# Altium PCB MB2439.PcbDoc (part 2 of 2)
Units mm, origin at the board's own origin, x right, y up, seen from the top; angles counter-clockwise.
Board outline 43.1 x 47.12 mm, 4 copper layers (Top Layer, Internal 2, Internal 3, Bottom Layer), stack 1.565 mm thick; 79 components, 62 nets, 323 pads, 761 vias.
Unrouted connection lines stored in the file: 15.
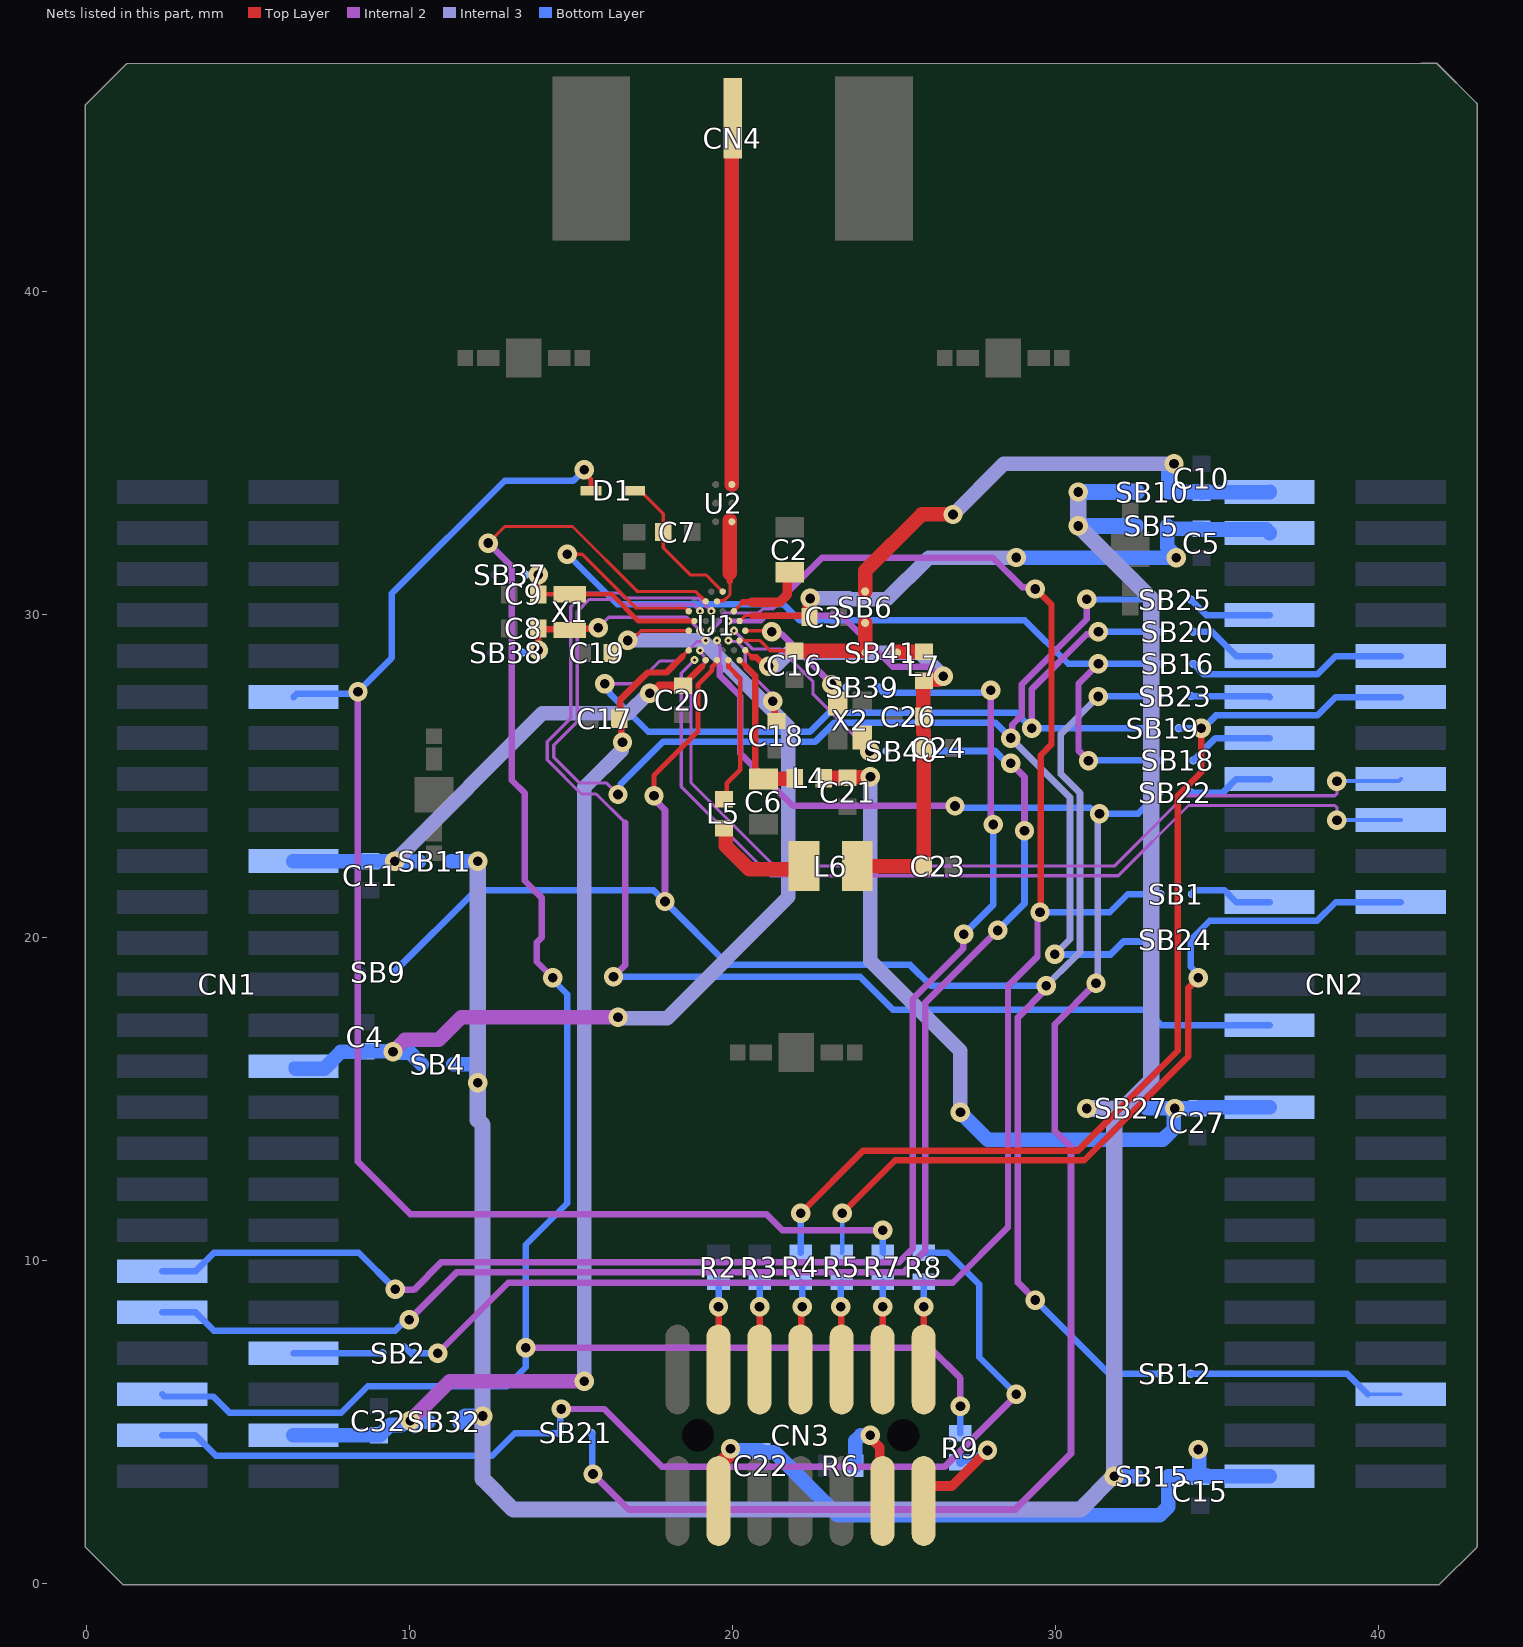
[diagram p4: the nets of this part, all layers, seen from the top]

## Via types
v1: diameter 0.6, hole 0.3, Top Layer to Bottom Layer, tented both sides, 747 vias
v2: diameter 0.25, hole 0.1, Top Layer to Internal 2, 14 vias

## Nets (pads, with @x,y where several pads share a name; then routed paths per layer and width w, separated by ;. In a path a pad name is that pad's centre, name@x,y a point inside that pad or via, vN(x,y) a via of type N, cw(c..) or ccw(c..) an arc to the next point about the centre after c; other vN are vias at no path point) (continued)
GPIO22: CN1.44 SB2.1 | length 2.8
  Bottom Layer w0.2: CN1.44@6.398,7.118 SB2.1@9.156,7.118
GPIO23: CN1.45 R9.1 U1.H2 | length 62.8
  Top Layer w0.1: v1(12.432,32.207) 12.944,32.72 15.039,32.72 17.055,30.703 18.86,30.703 U1.H2@19.163,30.4
  Internal 2 w0.2: v1(12.432,32.207) 13.161,31.478 13.161,24.864 13.557,24.467 13.557,21.755 14.093,21.218 14.093,20.005 13.929,19.841 13.929,19.246 v1(14.429,18.746) ; v1(13.593,7.293) 26.108,7.293 27.051,6.35 v1(27.051,5.477) v1@27.051,5.393
  Bottom Layer w0.2: CN1.45@2.334,5.848 2.403,5.78 3.914,5.78 4.414,5.28 7.878,5.28 8.694,6.096 13.001,6.096 13.593,6.687 13.593,10.48 14.876,11.762 14.876,18.234 14.429,18.681 v1(14.429,18.746) ; R9.1@27.051,4.641 v1(27.051,5.477)
GPIO24: CN1.47 R8.2 SB21.1 | length 35.5
  Internal 2 w0.2: v1(14.691,5.393) 16.019,5.393 17.803,3.609 26.571,3.609 v1@28.88,5.918
  Bottom Layer w0.2: CN1.47@2.334,4.578 3.363,4.578 3.997,3.944 12.55,3.944 13.249,4.644 14.657,4.644 14.657,5.359 v1(14.691,5.393) ; R8.2@25.917,10.229 26.655,10.229 27.635,9.249 27.635,6.991 v1(28.778,5.848)
GPIO28: CN2.7 SB25.1 | length 2.6
  Bottom Layer w0.2: SB25.1@34.186,30.457 34.664,29.978 CN2.7@36.624,29.978
GPIO29: CN2.9 SB20.2 | length 2.7
  Bottom Layer w0.2: SB20.2@34.261,29.461 34.843,29.461 35.596,28.708 CN2.9@36.624,28.708
GPIO30: CN2.10 SB16.2 | length 6.8
  Bottom Layer w0.2: SB16.2@34.261,28.466 34.587,28.14 38.104,28.14 38.673,28.708 CN2.10@40.688,28.708
GPIO31: CN2.11 SB23.1 | length 2.5
  Bottom Layer w0.2: SB23.1@34.186,27.47 36.593,27.47 CN2.11@36.624,27.438
GPIO32: CN2.12 R4.2 SB19.2 | length 32.6
  Top Layer w0.2: v1(22.103,11.455) 24.042,13.394 30.692,13.394 33.782,16.485 33.782,24.383 34.511,25.112 v1(34.511,26.474)
  Bottom Layer w0.2: R4.2@22.103,10.229 v1(22.103,11.455) ; SB19.2@33.811,26.474 v1(34.511,26.474) 34.568,26.474 34.964,26.87 38.104,26.87 38.673,27.438 CN2.12@40.688,27.438
GPIO33: CN2.13 SB18.2 | length 2.6
  Bottom Layer w0.2: SB18.2@34.261,25.479 34.95,26.168 CN2.13@36.624,26.168
GPIO34: CN2.15 SB22.1 | length 2.6
  Bottom Layer w0.2: SB22.1@34.186,24.483 35.181,24.483 35.596,24.898 CN2.15@36.624,24.898
GPIO37: CN2.21 SB1.1 | length 2.6
  Bottom Layer w0.2: SB1.1@34.223,21.336 34.223,21.35 34.288,21.415 34.288,21.457 35.228,21.457 35.596,21.088 CN2.21@36.624,21.088
GPIO38: CN2.22 R5.2 SB24.1 | length 24.8
  Top Layer w0.2: v1(23.393,11.455) 25.032,13.094 30.889,13.094 34.111,16.317 34.111,18.429 34.417,18.735 v1(34.417,18.746)
  Bottom Layer w0.15: R5.2@23.374,10.229 23.393,10.248 v1(23.393,11.455)
  Bottom Layer w0.2: v1(34.417,18.746) 34.417,18.854 34.186,19.085 SB24.1@34.186,19.921 34.774,20.51 38.094,20.51 38.673,21.088 CN2.22@40.688,21.088
GPIO42: CN2.27 U1.G3 | length 38.9
  Internal 2 w0.1: 16.667,23.54 15.77,24.437 15.315,24.437 14.258,25.494 14.258,26.061 14.982,26.785 14.982,30.235 15.41,30.663 16.494,30.663 16.649,30.509 18.44,30.509 18.93,30.509 v2@19.338,30.101
  Internal 2 w0.2: v1(16.31,18.778) 16.667,19.135 16.667,23.54
  Bottom Layer w0.2: v1(16.31,18.778) 23.942,18.778 24.957,17.763 32.802,17.763 33.286,17.278 CN2.27@36.624,17.278
  other v2: 19.338,30.097
GPIO56: CN2.46 SB12.1 | length 6.8
  Bottom Layer w0.1: CN2.46@39.66,5.848 CN2.46@40.688,5.848
  Bottom Layer w0.2: SB12.1@34.186,6.483 39.025,6.483 CN2.46@39.66,5.848
NetC2_2: C2.2 U1.C3 | length 2.8
  Top Layer w0.1: U1.C3@20.038,30.097 20.312,30.372 ; C2.2@21.689,31.031 21.959,31.3 C2.2@22.1,31.3
  Top Layer w0.2: 20.312,30.372 20.599,30.372
  Top Layer w0.3: 20.599,30.372 21.45,30.372 21.689,30.61 C2.2@21.689,31.031
NetC6_1: C6.1 L4.2 U1.B8 | length 5
  Top Layer w0.15: U1.B8@20.213,28.582 20.416,28.379
  Top Layer w0.2: 20.416,28.379 20.697,28.098 20.697,25.12 20.917,24.9 C6.1@20.955,24.9
  Top Layer w0.45: C6.1@20.955,24.9 20.968,24.912 21.906,24.912 L4.2@21.919,24.925
NetC7_2: C7.2 D1.1 U1.E1 | length 4.6
  Top Layer w0.1: D1.1@16.956,33.831 17.131,33.831 17.847,33.115 C7.2@17.847,32.546 17.847,32.059 18.686,31.22 19.171,31.22 19.479,30.912 U1.E1@19.688,30.703
NetC8_2: C8.2 SB38.1 U1.J5 X1.2 | length 6.6
  Top Layer w0.2: v1(13.979,28.885) C8.2@13.979,29.567 14.002,29.544 14.934,29.544 X1.2@14.958,29.52 14.988,29.55 15.802,29.55 v1(15.832,29.58)
  Internal 2 w0.1: v1(15.832,29.58) 16.161,29.909 18.44,29.909 18.57,29.909 v2(18.988,29.491)
  Bottom Layer w0.15: SB38.1@13.48,28.816 13.909,28.816 v1(13.979,28.885)
NetC9_2: C9.2 SB37.1 U1.K4 X1.1 | length 5.8
  Top Layer w0.15: v1(13.979,31.228) C9.2@13.979,30.62 X1.1@14.958,30.62 16.254,30.62 17.08,29.794 U1.K4@18.799,29.794
NetC16_2: C16.2 SB6.2 SB41.1 U1.B6 | length 4.8
  Top Layer w0.1: U1.B6@20.213,29.188 20.848,29.188 21.161,28.875 C16.2@21.919,28.875
  Top Layer w0.45: C16.2@21.919,28.875 24.054,28.875 24.101,28.921 SB6.2@24.101,29.734
NetC23_2: C23.2 C24.1 C26.1 L6.2 L7.2 U1.A7 U1.D4 | length 22.7
  Top Layer w0.1: U1.A7@20.388,28.885 20.599,28.674
  Top Layer w0.2: 20.599,28.674 20.727,28.674 21.005,28.395 v1(21.113,28.395)
  Top Layer w0.45: L6.2@23.859,22.205 C23.2@25.909,22.205 C24.1@25.909,25.826 ; C24.1@25.915,25.864 25.915,26.355 25.907,26.363 25.907,26.834 25.907,27.936 25.947,27.975 26.375,27.975 26.482,28.082 v1(26.522,28.082)
  Internal 2 w0.15: v2(19.863,29.794) 20.873,29.794 21.015,29.936 21.359,29.936 21.374,29.952 ; v1@26.401,28.082 v1(26.522,28.082)
  Internal 2 w0.2: 21.374,29.952 23.38,29.952 24.955,28.377 26.106,28.377 v1@26.401,28.082
  Internal 3 w0.45: v1(21.113,28.395) 21.142,28.424 21.345,28.424 21.736,28.816 25.789,28.816 v1(26.522,28.082)
NetCN3_4: CN3.4 R2.1 | length 2.7
  Top Layer w0.2: CN3.4@19.561,6.614 v1(19.561,8.563)
  Bottom Layer w0.2: v1(19.561,8.563) R2.1@19.561,9.329
NetCN3_6: CN3.6 R3.1 | length 2.7
  Top Layer w0.2: CN3.6@20.831,6.614 v1(20.831,8.563)
  Bottom Layer w0.2: v1(20.831,8.563) R3.1@20.831,9.328
NetCN3_8: CN3.8 R4.1 | length 2.8
  Top Layer w0.2: CN3.8@22.101,6.614 22.125,6.638 22.125,8.539 v1(22.149,8.563)
  Bottom Layer w0.2: R4.1@22.103,9.329 22.149,9.283 v1(22.149,8.563)
NetCN3_10: CN3.10 R5.1 | length 2.7
  Top Layer w0.2: v1(23.346,8.563) 23.359,8.551 23.359,6.627 CN3.10@23.371,6.614
  Bottom Layer w0.2: v1(23.346,8.563) 23.346,9.301 R5.1@23.374,9.329
NetCN3_11: CN3.11 R6.2 | length 3.5
  Top Layer w0.3: v1(24.259,4.579) 24.259,4.498 24.557,4.2 24.557,2.629 CN3.11@24.641,2.544
  Bottom Layer w0.3: v1@23.971,4.578 24.258,4.578 v1(24.259,4.579)
  Bottom Layer w0.45: R6.2@23.795,3.631 23.795,4.403 v1@23.971,4.578
NetCN3_12: CN3.12 R7.1 | length 2.7
  Top Layer w0.2: CN3.12@24.641,6.614 24.644,6.616 24.644,8.561 v1(24.646,8.563)
  Bottom Layer w0.2: v1(24.646,8.563) R7.1@24.646,9.329
NetCN3_13: CN3.13 R9.2 | length 3.8
  Top Layer w0.3: CN3.13@25.911,2.544 25.911,2.805 26.115,3.008 26.786,3.008 v1(27.888,4.109)
  Bottom Layer w0.3: R9.2@27.057,3.747 27.156,3.846 27.562,3.846 27.826,4.109 v1(27.888,4.109)
NetCN3_14: CN3.14 R8.1 | length 2.7
  Top Layer w0.2: CN3.14@25.911,6.614 25.914,6.617 25.914,8.561 v1(25.917,8.563)
  Bottom Layer w0.2: v1(25.917,8.563) R8.1@25.917,9.329
NetCN4_1: CN4.1 U2.A3 | length 11.4
  Top Layer w0.45: U2.A3@19.972,34.02 19.972,45.332 CN4.1@20,45.36
NetL5_1: L5.1 U1.D8 | length 4.7
  Top Layer w0.15: L5.1@19.728,24.275 19.815,24.362 19.815,24.772 20.235,25.192 20.235,28.01 19.871,28.374 19.871,28.379 U1.D8@19.871,28.57
NetL5_2: L5.2 L6.1 | length 3.3
  Top Layer w0.45: L5.2@19.728,23.375 19.747,23.375 19.777,23.345 19.777,22.835 20.508,22.105 21.959,22.105 22.06,22.205 L6.1@22.209,22.205
NetL7_1: L7.1 SB41.2 | length 0.8
  Top Layer w0.3: SB41.2@25.088,28.816 SB41.2@25.118,28.845
  Top Layer w0.45: SB41.2@25.118,28.845 L7.1@25.917,28.845
NetSB1_2: SB1.2 SB2.2 U1.G5 | length 56.3
  Top Layer w0.2: v1(29.367,30.785) 29.384,30.785 29.871,30.298 29.871,25.977 29.534,25.64 29.534,20.797 v1(29.515,20.777)
  Internal 2 w0.1: v2(19.338,29.491) 19.338,29.495 19.613,29.77 19.613,29.898 19.759,30.044 20.599,30.044 20.804,30.044 20.921,30.161 21.123,30.161 21.173,30.211
  Internal 2 w0.2: v1(10.866,7.118) 13.051,9.304 26.809,9.304 28.524,11.019 28.524,18.49 29.438,19.404 29.438,20.701 v1(29.515,20.777) ; 21.223,30.211 22.765,31.753 28.052,31.753 28.97,30.836 29.316,30.836 v1(29.367,30.785)
  Bottom Layer w0.2: 9.809,7.341 SB2.2@10.081,7.068 ; SB2.2@10.131,7.118 v1(10.866,7.118) ; v1(29.515,20.777) 31.671,20.777 32.229,21.336 SB1.2@33.248,21.336
NetSB4_1: SB4.1 SB5.1 SB10.1 SB11.1 SB15.1 SB27.1 SB32.1 | length 81
  Internal 3 w0.5: v1@12.087,22.357 12.103,22.34 v1(12.103,15.494) 12.103,14.346 12.255,14.194 v1(12.255,5.173) 12.255,3.234 13.21,2.279 30.759,2.279 31.788,3.308 v1(31.815,3.308) 31.815,14.68 ; v1(30.7,33.788) v1(30.7,32.738) 32.959,30.479 32.959,15.569 31.967,14.577 31.864,14.68 31.815,14.68 ; 31.294,14.719 30.982,14.719 v1(30.963,14.699) 30.982,14.68 31.815,14.68
  Bottom Layer w0.45: SB11.1@11.266,22.358 12.101,22.358 v1(12.103,22.357) ; SB4.1@11.347,16.07 11.349,16.072 12.024,16.072 ; v1(31.815,3.308) SB15.1@32.511,3.308
  Bottom Layer w0.5: SB32.1@11.559,4.998 11.715,5.154 12.236,5.154 v1(12.255,5.173) ; 12.024,16.072 12.084,16.012 12.084,15.513 v1(12.103,15.494) ; v1(30.7,32.738) SB5.1@32.481,32.738 ; v1(30.7,33.788) SB10.1@32.509,33.788 ; v1(30.963,14.699) SB27.1@31.85,14.699
NetSB9_2: SB9.2 SB12.2 SB23.2 U1.F8 | length 58
  Top Layer w0.15: v1(17.563,24.381) 17.563,25.013 18.922,26.372 18.922,27.826 19.363,28.267 19.363,28.378 19.503,28.518 19.503,28.573 U1.F8@19.513,28.582
  Internal 2 w0.21: v1(17.563,24.381) 17.563,24.275 17.901,23.937 v1(17.901,21.107) ; v1(29.367,8.765) 28.829,9.304 28.829,17.515 29.707,18.393 v1(29.707,18.498)
  Internal 3 w0.21: v1(29.707,18.498) 30.173,18.965 30.181,18.965 30.752,19.535 30.752,24.462 30.159,25.054 30.159,26.299 v1(31.318,27.457)
  Bottom Layer w0.21: SB9.2@9.513,18.921 12.048,21.457 17.551,21.457 v1(17.901,21.107) 19.862,19.146 25.488,19.146 26.136,18.498 v1(29.707,18.498) ; v1(29.367,8.765) 31.649,6.483 SB12.2@33.211,6.483 ; v1(31.318,27.457) 31.325,27.464 33.205,27.464 SB23.2@33.211,27.47
NetSB16_1: SB16.1 SB18.1 U1.L3 | length 30
  Top Layer w0.1: v1(14.878,31.857) 15.335,31.857 16.992,30.2 18.529,30.2 18.632,30.097 U1.L3@18.638,30.097
  Internal 2 w0.2: v1(31.015,25.466) 31.015,25.476 30.708,25.783 30.708,27.849 v1(31.325,28.466)
  Bottom Layer w0.2: v1(14.878,31.857) 16.422,30.313 18.44,30.313 20.599,30.313 21.574,30.313 22.076,29.811 29.046,29.811 30.392,28.466 v1(31.325,28.466) SB16.1@33.286,28.466 ; v1(31.015,25.466) 31.028,25.479 SB18.1@33.286,25.479
NetSB19_1: SB19.1 SB20.1 U1.H6 | length 27.6
  Internal 2 w0.1: v1(16.039,27.848) 17.039,27.848 17.747,28.556 18.3,28.556 18.44,28.696 18.904,29.16 19.134,29.16 v2(19.163,29.188)
  Internal 2 w0.2: v1(29.255,26.474) 29.255,27.675 30.965,29.385 31.248,29.385 v1(31.325,29.461)
  Bottom Layer w0.2: v1(16.039,27.848) 16.039,27.74 16.192,27.587 16.192,27.552 17.383,26.361 22.39,26.361 22.979,26.949 27.217,26.949 28.78,26.949 v1(29.255,26.474) SB19.1@32.836,26.474 ; v1(31.325,29.461) SB20.1@33.286,29.461
NetSB21_2: SB21.2 SB22.2 U1.F6 | length 55.7
  Internal 2 w0.1: v2(19.513,29.188) 19.513,29.148 19.604,29.057 19.604,28.379
  Internal 2 w0.2: 19.604,28.379 19.604,28.095 20.233,27.466 20.233,25.69 21.857,24.066 v1(26.881,24.066)
  Internal 2 w0.21: v1(15.672,3.378) 16.771,2.279 28.746,2.279 30.477,4.01 30.477,13.502 29.972,14.007 29.972,17.301 v1(31.249,18.578)
  Internal 3 w0.21: v1(31.249,18.578) 31.304,18.633 31.304,23.77 v1(31.359,23.825)
  Bottom Layer w0.1: SB21.2@15.622,4.654 SB21.2@15.647,4.629 ; v1@15.647,3.403 v1(15.672,3.378)
  Bottom Layer w0.2: v1@15.647,3.403 SB21.2@15.647,4.629 ; v1(26.881,24.066) 26.939,24.008 31.069,24.008 31.251,23.825 32.553,23.825 SB22.2@33.211,24.483
NetSB24_2: SB24.2 SB25.2 U1.J3 | length 43.4
  Internal 2 w0.1: v1(16.449,24.42) 16.093,24.776 15.259,24.776 14.458,25.577 14.458,25.951 15.182,26.676 15.182,30.082 15.564,30.463 16.411,30.463 16.566,30.309 18.776,30.309 v2(18.988,30.097)
  Internal 2 w0.2: v1(28.607,26.168) 28.657,26.218 28.657,26.583 28.955,26.881 28.955,27.839 30.963,29.846 v1(30.963,30.463)
  Internal 3 w0.21: v1(28.607,26.168) 30.442,24.334 30.442,19.94 v1(29.972,19.47)
  Bottom Layer w0.2: v1(16.449,24.42) 16.525,24.496 16.525,24.738 17.848,26.061 22.561,26.061 23.149,26.649 28.126,26.649 v1(28.607,26.168) ; v1(30.963,30.463) 30.966,30.46 33.208,30.46 SB25.2@33.211,30.457 ; 32.753,19.869 32.845,19.869 32.897,19.921 SB24.2@33.211,19.921
  Bottom Layer w0.21: v1(29.972,19.47) 31.703,19.469 32.103,19.869 32.753,19.869
NetSB39_1: SB39.1 U1.A5 X2.3 | length 4
  Top Layer w0.1: U1.A5@20.388,29.491 21.181,29.491 v1(21.211,29.461)
  Top Layer w0.2: v1@23.076,27.818 23.068,27.81 23.068,27.427 X2.3@23.257,27.238
  Internal 2 w0.2: v1(21.211,29.461) 21.288,29.385 21.525,29.385 23.068,27.841 v1(23.068,27.826)
NetSB40_1: SB40.1 U1.C5 X2.1 | length 6
  Internal 2 w0.1: v2@20.041,29.491 20.041,29.488 20.599,28.93 21.477,28.93 22.488,27.918 22.488,27.523 v1(24.247,25.765)
  other v2: 20.038,29.491
NetU1_F2: U1.F2 U2.A1 | length 2.8
  Top Layer w0.1: U1.F2@19.513,30.4 19.532,30.419 19.722,30.419 19.915,30.612 19.915,31.02
  Top Layer w0.2: 19.915,31.02 19.915,31.265
  Top Layer w0.45: U2.A1@19.913,32.918 19.913,31.325 19.915,31.323 19.915,31.265
NRST: CN1.12 D1.2 R7.2 | length 46.2
  Top Layer w0.15: v1(15.406,34.475) 15.406,34.38 15.606,34.179 D1.2@15.606,33.831
  Internal 2 w0.2: v1(8.395,27.601) 8.395,13.049 10.016,11.428 21.039,11.428 21.539,10.928 v1(24.646,10.928)
  Bottom Layer w0.2: CN1.12@6.398,27.438 6.502,27.542 8.337,27.542 v1(8.395,27.601) 9.444,28.65 9.444,30.643 12.938,34.138 15.068,34.138 v1(15.406,34.475) ; R7.2@24.646,10.229 v1(24.646,10.928)
OSC_IN: CN1.39 SB39.2 | length 46.4
  Internal 2 w0.21: v1@9.569,9.083 10.125,9.083 10.981,9.94 25.156,9.94 25.578,10.362 25.578,18.097 27.142,19.661 27.142,20.082 v1(27.156,20.096) ; v1(27.991,27.645) 27.991,23.812 27.996,23.807 27.996,23.569 v1(28.07,23.494)
  Bottom Layer w0.21: CN1.39@2.334,9.658 3.363,9.658 3.936,10.232 8.42,10.232 v1(9.554,9.097) v1@9.542,9.085 ; SB39.2@24.496,27.74 24.661,27.575 27.921,27.575 v1(27.991,27.645) ; v1(27.156,20.096) 28.07,21.011 v1(28.07,23.494)
OSC_OUT: CN1.41 SB40.2 | length 44.5
  Internal 2 w0.21: v1(9.982,8.153) 11.459,9.63 25.302,9.63 25.959,10.287 25.959,17.968 v1(28.203,20.212) ; v1(28.607,25.387) 29.034,24.959 v1(29.034,23.3)
  Bottom Layer w0.21: CN1.41@2.334,8.388 3.363,8.388 3.936,7.815 9.538,7.815 9.877,8.153 v1(9.982,8.153) ; SB40.2@25.736,25.765 28.123,25.765 28.502,25.387 v1(28.607,25.387) ; v1(28.203,20.212) 29.034,21.044 v1(29.034,23.3)
USB_FS_N: CN2.18 U1.K8 | length 28.8
  Internal 2 w0.1: v2(18.813,28.582) 18.61,28.379 18.408,28.178 18.408,24.665 21.17,21.903 31.937,21.903 34.114,24.081 38.651,24.081 38.71,24.022 v1(38.71,23.628)
  Bottom Layer w0.127: v1(38.71,23.628) CN2.18@40.688,23.628
USB_FS_P: CN2.16 U1.J7 | length 28.7
  Internal 2 w0.1: v2@18.989,28.877 18.989,28.843 19.06,28.771 19.06,28.759 19.113,28.707 19.113,28.458 19.034,28.379 18.708,28.053 18.708,24.789 21.294,22.203 31.812,22.203 33.99,24.381 38.651,24.381 38.71,24.439 v1(38.71,24.833)
  Bottom Layer w0.127: v1(38.71,24.833) 40.623,24.833 CN2.16@40.688,24.898
  other v2: 18.992,28.88
VDD4: C4.2 C18.1 C19.1 CN1.30 SB4.2 U1.D6 U1.L5 | length 35.9
  Top Layer w0.1: C19.1@16.261,28.804 16.261,28.792 16.306,28.747 v1(16.751,29.192) 16.86,29.192 17.159,29.491 U1.L5@18.638,29.491
  Top Layer w0.2: v1(21.239,27.308) 21.295,27.252 21.295,26.753 C18.1@21.351,26.697
  Internal 2 w0.1: v2(19.863,29.188) 19.891,29.159 20.117,29.159 20.388,28.889 20.388,28.323 21.159,27.552 21.159,27.389 v1(21.239,27.308)
  Internal 2 w0.45: v1(9.481,16.459) 9.85,16.828 10.901,16.828 11.597,17.524 v1(16.449,17.524)
  Internal 3 w0.45: v1(16.449,17.524) 16.477,17.495 17.969,17.495 21.726,21.252 21.726,26.521 19.868,28.379 19.056,29.192 v1@16.791,29.192
  Bottom Layer w0.3: CN1.30@6.398,16.008 CN1.30@6.476,15.931
  Bottom Layer w0.45: CN1.30@6.476,15.931 7.349,15.931 7.867,16.448 8.607,16.448 C4.2@8.627,16.469 v1@9.512,16.469 ; v1(9.481,16.459) 9.51,16.431 10.013,16.431 SB4.2@10.372,16.07 SB4.2@10.372,16.07
VDD5: C3.1 C5.2 CN2.3 SB5.2 U1.B4 | length 19.1
  Top Layer w0.1: U1.B4@20.213,29.794 20.38,29.961 20.599,29.961
  Top Layer w0.2: 20.599,29.961 22.33,29.961 C3.1@22.377,29.914
  Top Layer w0.45: C3.1@22.377,29.914 22.389,29.926 22.389,30.481 v1(22.4,30.493)
  Internal 3 w0.45: v1(22.4,30.493) 23.593,30.493 23.622,30.463 24.774,30.463 26.069,31.759 v1(28.78,31.759)
  Bottom Layer w0.45: v1(28.78,31.759) v1(33.736,31.757) ; v1(33.736,31.757) 33.736,31.798 33.456,32.078 SB5.2@33.456,32.738 33.537,32.657 C5.2@34.519,32.657 34.549,32.627 36.516,32.627 CN2.3@36.624,32.518
VDD8: C17.1 C32.2 CN1.48 SB32.2 U1.L7 | length 34.9
  Top Layer w0.1: 18.44,28.688 U1.L7@18.638,28.885
  Top Layer w0.2: v1(16.586,26.039) 16.554,26.071 16.554,26.702 16.464,26.791 16.512,26.839 16.512,27.346 17.223,28.057 17.226,28.057 17.367,28.199 17.951,28.199 18.44,28.688
  Internal 2 w0.45: v1(10.013,5.027) 11.24,6.254 v1(15.406,6.254)
  Internal 3 w0.45: v1(15.406,6.254) 15.406,24.639 16.558,25.791 16.558,26.01 v1(16.586,26.039)
  Bottom Layer w0.45: CN1.48@6.398,4.578 9.043,4.578 9.069,4.577 9.389,4.897 9.729,4.897 9.831,4.998 9.984,4.998 v1(10.013,5.027) 10.041,4.998 SB32.2@10.584,4.998 ; v1@10.013,4.987 v1@10.147,4.853
VDD9: C21.1 C27.2 CN2.31 L4.1 SB27.2 | length 24.6
  Top Layer w0.45: L4.1@22.819,24.925 22.829,24.935 23.549,24.935 23.575,24.962 24.215,24.962 v1@24.243,24.989
  Internal 3 w0.45: v1(24.264,24.969) 24.264,19.277 27.051,16.49 v1(27.051,14.577)
  Bottom Layer w0.45: v1(27.051,14.577) 27.903,13.726 33.317,13.726 33.663,14.072 33.663,14.671 v1(33.692,14.699) ; SB27.2@32.825,14.699 v1(33.692,14.699) ; CN2.31@36.624,14.738 34.456,14.738 34.417,14.699 C27.2@34.392,14.699 v1(33.692,14.699)
VDD10: C10.2 CN2.1 SB6.1 SB10.2 | length 15.7
  Top Layer w0.45: SB6.1@24.101,30.709 24.101,31.347 25.847,33.093 v1(26.822,33.093)
  Internal 3 w0.45: v1(26.822,33.093) 28.391,34.661 v1(33.663,34.661)
  Bottom Layer w0.45: v1(33.663,34.661) 33.663,34.62 33.484,34.441 SB10.2@33.484,33.788 34.491,33.788 C10.2@34.519,33.761 34.532,33.775 36.611,33.775 CN2.1@36.624,33.788
VDD15: C15.2 C22.1 CN2.49 CN3.3 SB15.2 | length 21.2
  Top Layer w0.45: CN3.3@19.561,2.544 19.561,3.648 19.903,3.989 19.903,4.13 v1(19.931,4.159)
  Bottom Layer w0.45: v1(19.931,4.159) 19.972,4.159 20.02,4.111 20.857,4.111 20.917,4.051 21.299,4.051 23.249,2.101 33.222,2.101 33.486,2.365 SB15.2@33.486,3.308 C15.2@34.464,3.308 ; v1(34.417,4.14) 34.448,4.109 34.448,3.325 C15.2@34.464,3.308 ; C15.2@34.478,3.295 C15.2@34.464,3.308 ; C15.2@34.478,3.308 CN2.49@36.624,3.308
VDDA: C11.2 C20.2 CN1.20 SB11.2 U1.H8 | length 16.1
  Top Layer w0.1: 19.034,28.379 19.163,28.508 U1.H8@19.163,28.582
  Top Layer w0.2: C20.2@18.492,27.8 18.635,27.942 18.635,27.98 19.034,28.379
  Top Layer w0.3: v1(17.431,27.559) 17.512,27.559 17.725,27.771 18.325,27.771 18.341,27.787 C20.2@18.455,27.787
  Internal 3 w0.45: v1(9.531,22.358) 14.106,26.933 16.765,26.933 17.391,27.559 v1(17.431,27.559)
  Bottom Layer w0.45: CN1.20@6.398,22.358 v1(9.531,22.358) SB11.2@10.291,22.358
pads on no net: CN1.2 CN1.3 CN1.4 CN1.5 CN1.8 CN1.10 CN1.11 CN1.16 CN1.18 CN1.19 CN1.21 CN1.23 CN1.24 CN1.27 CN1.29 CN1.32 CN1.36 CN1.38 CN1.42 CN1.43 CN1.50 CN2.4 CN2.5 CN2.6 CN2.17 CN2.19 CN2.23 CN2.24 CN2.25 CN2.28 CN2.29 CN2.30 CN2.33 CN2.34 CN2.35 CN2.36 CN2.37 CN2.39 CN2.40 CN2.41 CN2.42 CN2.43 CN2.45 CN2.47 CN2.48 CN3.1 CN3.2 CN3.9 CN3.NPTH1 CN3.NPTH2

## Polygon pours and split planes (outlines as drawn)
GND on Top Layer "GND_L01_P000" (solid, pour order 0): -0.036,1.103 cw(c0,1.139) -0.05,1.139 -0.05,45.75 -0.05,45.755 cw(c0,45.755) -0.035,45.791 1.209,47.036 cw(c1.245,47) 1.245,47.05 41.326,47.066 41.78,47.066 cw(c41.78,47.015) 41.816,47.051 43.03,45.837 cw(c43.001,45.795) 43.051,45.795 cw(c43.002,45.795) 43.05,45.785 43.05,1.151 cw(c43.002,1.141) 43.051,1.141 cw(c43.001,1.141) 43.037,1.105 41.888,-0.036 cw(c41.852,0) 41.852,-0.05 1.139,-0.05 cw(c1.139,0) 1.103,-0.036
GND on Internal 3 "GND_L03_P002" (solid, pour order 2): -0.036,1.103 cw(c0,1.139) -0.05,1.139 -0.05,45.75 -0.05,45.755 cw(c0,45.755) -0.035,45.791 1.209,47.036 cw(c1.245,47) 1.245,47.05 41.326,47.066 41.78,47.066 cw(c41.78,47.015) 41.816,47.051 43.03,45.837 cw(c43.001,45.795) 43.051,45.795 cw(c43.002,45.795) 43.05,45.785 43.05,1.151 cw(c43.002,1.141) 43.051,1.141 cw(c43.001,1.141) 43.037,1.105 41.888,-0.036 cw(c41.852,0) 41.852,-0.05 1.139,-0.05 cw(c1.139,0) 1.103,-0.036
GND on Bottom Layer "GND_L04_P003" (solid, pour order 3): -0.036,1.103 cw(c0,1.139) -0.05,1.139 -0.05,45.75 -0.05,45.755 cw(c0,45.755) -0.035,45.791 1.209,47.036 cw(c1.245,47) 1.245,47.05 41.326,47.066 41.78,47.066 cw(c41.78,47.015) 41.816,47.051 43.03,45.837 cw(c43.001,45.795) 43.051,45.795 cw(c43.002,45.795) 43.05,45.785 43.05,1.151 cw(c43.002,1.141) 43.051,1.141 cw(c43.001,1.141) 43.037,1.105 41.888,-0.036 cw(c41.852,0) 41.852,-0.05 1.139,-0.05 cw(c1.139,0) 1.103,-0.036
GND on Internal 2 "GND_L02_P001" (solid, pour order 1): -0.036,1.103 cw(c0,1.139) -0.05,1.139 -0.05,45.75 -0.05,45.755 cw(c0,45.755) -0.035,45.791 1.209,47.036 cw(c1.245,47) 1.245,47.05 41.326,47.066 41.78,47.066 cw(c41.78,47.015) 41.816,47.051 43.03,45.837 cw(c43.001,45.795) 43.051,45.795 cw(c43.002,45.795) 43.05,45.785 43.05,1.151 cw(c43.002,1.141) 43.051,1.141 cw(c43.001,1.141) 43.037,1.105 41.888,-0.036 cw(c41.852,0) 41.852,-0.05 1.139,-0.05 cw(c1.139,0) 1.103,-0.036

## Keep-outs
Keep-Out Layer:
  lines w0.1: 1.245,46.99 41.859,46.99 ; 43.001,1.143 43.001,45.798 41.781,47.018 1.261,47.018 0.001,45.757 0.001,1.141 1.14,0.002 11.318,0.002 11.329,0.013 16.413,0.013 26.58,0.013 31.664,0.013 31.675,0.002 41.853,0.002 42.505,0.65 43.002,1.143

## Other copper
Top Layer:
  pour cut-out: 2.179,43.064 2.179,45.096 7.656,45.096 7.656,43.064
  pour cut-out: 20.568,30.189 20.468,30.22 20.397,30.22 20.18,30.259 19.857,30.426 19.481,30.846 18.415,30.886 18.413,30.884 18.413,28.392 20.597,28.392 20.604,28.399 20.604,30.259
  text "1" at 2.422,43.483 h2
  text ".Layer_Name" at -14.442,-71.206 h3
  text ".GTL" at 27.253,-71.206 h3
Internal 2:
  pour cut-out: 2.179,43.064 2.179,45.096 7.656,45.096 7.656,43.064
  pour cut-out: 18.8,47 21.2,47 21.2,29.794 18.8,29.794
  text "2" at 3.664,43.483 h2
  text ".Layer_Name" at -14.442,-71.206 h3
  text ".G1" at 27.253,-71.206 h3
Internal 3:
  pour cut-out: 2.179,43.064 2.179,45.096 7.656,45.096 7.656,43.064
  text "3" at 5.17,43.507 h2
Bottom Layer:
  pour cut-out: 2.179,43.064 2.179,45.096 7.656,45.096 7.656,43.064
  text "4" at 6.508,43.536 h2
  text ".GBL" at 16.05,-71.238 h3
  text ".Layer_Name" at 57.364,-71.238 h3

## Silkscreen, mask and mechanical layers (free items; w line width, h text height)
Top Overlay:
  text "J" at 34.163,40.615 h10
  text "K" at 1.803,36.652 h10
  text "MB2439B" at 32.512,1.337 h2.5
  text ".Layer_Name" at -14.442,-71.206 h3
  text ".GTO" at 27.253,-71.206 h3
Board Layer Stack Bottom Overlay:
  text "H" at 32.868,42.621 h7.62
  text "I" at 40.488,42.113 h7.62
  text "G" at 7.925,38.76 h7.62
  text ".GBO" at 16.05,-71.238 h3
  text ".Layer_Name" at 57.364,-71.238 h3
Top Paste:
  text ".Layer_Name" at -14.442,-71.206 h3
  text ".GTP" at 27.253,-71.206 h3
Bottom Paste:
  text ".GBP" at 16.05,-71.238 h3
  text ".Layer_Name" at 57.364,-71.238 h3
Top Solder:
  lines w0.75: 17.831,37.929 10.75,37.929 10.75,16.5 32.25,16.5 32.25,37.96 22.649,37.96
  text ".Layer_Name" at -14.442,-71.206 h3
  text ".GTS" at 27.253,-71.206 h3
Board Layer Stack Bottom Solder:
  text ".GBS" at 16.05,-71.238 h3
  text ".Layer_Name" at 57.364,-71.238 h3
M1-Board Shape:
  lines w0.1: 43.002,1.143 43.002,45.798 ; 43.003,1.143 41.854,0.002 1.141,0.002 0.002,1.141 0.002,45.752 1.252,47.002 41.328,47.018 41.782,47.018 41.989,46.811 43.002,45.798 ; 43.003,45.798 43.002,45.798
M2-Board Dimensions:
  lines w0.254: -5.798,2 -5.131,0 ; -5.797,45 -5.131,47 ; -5.385,0 -4.877,0 ; -5.385,47 -4.877,47 ; -5.131,19.955 -5.131,0 ; -5.131,27.045 -5.131,47 ; -4.464,2 -5.131,0 ; -4.464,45 -5.131,47 ; 0,-11.121 0,-10.613 ; 2,-11.534 0,-10.867 ; 2,-10.201 0,-10.867 ; 17.955,-10.867 0,-10.867 ; 25.045,-10.867 43,-10.867 ; 41,-11.534 43,-10.867 ; 41,-10.201 43,-10.867 ; 43,-11.121 43,-10.613
  text "47 (mm)" at -4.29,20.209 h2 r90
  text "43 (mm)" at 18.209,-11.708 h2
  text ".Layer_Name" at -14.442,-71.206 h3
  text ".GM2" at 27.253,-71.206 h3
M4-Bottom Dimensions:
  lines w0.254: 2.334,-5.254 2.334,-4.746 ; 4.334,-5.667 2.334,-5 ; 4.334,-4.333 2.334,-5 ; 14.717,-5 2.334,-5 ; 24.242,-5 36.624,-5 ; 34.624,-5.667 36.624,-5 ; 34.624,-4.333 36.624,-5 ; 36.624,-5.254 36.624,-4.746
  text "34.29 (mm)" at 14.971,-5.841 h2
  text "CN1/CN2 spacing" at 12.954,-7.595 h2
M15-Bottom Assembly:
  text ".GM15" at 16.05,-71.238 h3
  text ".Layer_Name" at 57.364,-71.238 h3
Drill Drawing:
  text ".Layer_Name" at -14.442,-71.206 h3
  text ".DRL" at 27.253,-71.206 h3
Top Assembly:
  text ".Layer_Name" at -14.442,-71.206 h3
  text ".GM14" at 27.253,-71.206 h3
M20-Top Title Box:
  circle w0.254: c63.562,-77.926 r1.3
  region: 49.084,-79.019 38.328,-79.019 39.322,-76.527 47.179,-76.527 47.628,-75.767 49.837,-78.316
  region: 63.088,-70.69 47.56,-70.69 46.866,-72.465 45.655,-73.69 44.258,-71.83 44.258,-70.179 45.401,-68.782 46.837,-68.404 63.088,-68.404
  lines w0.254: 39.322,-76.527 48.114,-76.527 45.047,-72.989 cw(c46.851,-71.045) 47.091,-68.404 63.855,-68.404 63.093,-70.69 ; 42.635,-68.157 cw(c45.062,-69.127) 45.298,-66.525 ; 42.675,-68.124 38.328,-79.019 57.651,-79.019 ccw(c57.9,-76.285) 60.449,-77.305 ; 44.414,-72.059 49.837,-78.316 ; 44.668,-72.059 49.973,-78.18 ; 44.668,-71.805 49.973,-77.926 ; 44.766,-70.69 57.759,-70.69 ; 44.795,-71.678 50.1,-77.799 ; 44.922,-71.551 50.227,-77.672 ; 45.049,-71.424 50.354,-77.545 ; 45.176,-71.297 50.481,-77.418 ; 45.231,-69.345 50.536,-75.466 ; 45.299,-66.525 64.749,-66.525 60.45,-77.302 ; 45.303,-71.17 50.554,-77.228 ; 45.303,-70.916 50.608,-77.037 ; 45.303,-70.662 50.608,-76.783 ; 45.303,-69.773 50.608,-75.894 ; 45.43,-70.535 50.735,-76.656 ; 45.43,-70.154 50.735,-76.275 ; 46.802,-76.54 ccw(c46.907,-76.005) 47.205,-75.548 ; 47.889,-70.677 ccw(c47.863,-71.244) 47.532,-71.706 49.897,-74.435 cw(c48.093,-76.378) 48.826,-78.927 ; 54.17,-78.815 57.059,-70.436 ; 54.392,-78.765 57.261,-70.445 ; 54.519,-78.765 57.388,-70.445 ; 54.773,-78.765 57.642,-70.445 ; 55.027,-78.765 57.896,-70.445 ; 55.281,-78.765 58.15,-70.445 ; 55.535,-78.765 58.404,-70.445 ; 55.789,-78.765 58.658,-70.445 ; 56.043,-78.765 58.912,-70.445 ; 56.297,-78.765 59.166,-70.445 ; 56.506,-78.815 59.395,-70.436 ; 59.395,-70.69 63.088,-70.69 ; 62.419,-70.687 63.181,-68.401 ; 62.585,-70.69 63.347,-68.404 ; 62.839,-70.69 63.601,-68.404
  lines w0.3: -23.442,-77.906 36.558,-77.906 ; -23.442,-72.906 36.558,-72.906 ; -23.442,-67.906 36.558,-67.906 ; 16.558,-82.906 16.558,-67.906 ; 36.558,-82.906 36.558,-62.906 ; 54.17,-78.815 56.506,-78.815 ; -23.442,-82.906 66.558,-82.906 66.558,-62.906 -23.442,-62.906 -23.442,-82.906
  text "Project: '.Board_Name'" at -22.442,-66.122 h3
  text "Layer:" at -22.442,-71.206 h3
  text "Gerber:" at 17.547,-71.206 h3
  text "Variant: '.VariantName'" at -22.442,-76.206 h3
  text "Ref: '.Board_Reference'" at 17.674,-76.206 h3
  text "R" at 63.054,-78.688 h1.52
  text "Date: '.Board_Document_Date'" at -22.442,-81.206 h3
  text "Rev: '.Board_PCB_Revision'" at 17.617,-81.206 h3
M21-Bottom Title Box:
  circle w0.254: c-20.259,-77.926 r1.3
  region: -19.784,-70.69 -4.257,-70.69 -3.563,-72.465 -2.352,-73.69 -0.955,-71.83 -0.955,-70.179 -2.098,-68.782 -3.534,-68.404 -19.784,-68.404
  region: -5.781,-79.019 4.975,-79.019 3.981,-76.527 -3.876,-76.527 -4.325,-75.767 -6.534,-78.316
  lines w0.254: -20.298,-68.404 -19.536,-70.69 ; -20.044,-68.404 -19.282,-70.69 ; -19.878,-68.401 -19.116,-70.687 ; -19.79,-70.69 -20.552,-68.404 -3.788,-68.404 cw(c-3.548,-71.045) -1.744,-72.989 -4.81,-76.527 3.981,-76.527 ; -19.784,-70.69 -16.092,-70.69 ; -17.147,-77.302 -21.446,-66.525 -1.996,-66.525 ; -17.146,-77.305 ccw(c-14.596,-76.285) -14.348,-79.019 4.975,-79.019 0.629,-68.124 ; -16.092,-70.436 -13.203,-78.815 ; -15.863,-70.445 -12.994,-78.765 ; -15.609,-70.445 -12.74,-78.765 ; -15.355,-70.445 -12.486,-78.765 ; -15.101,-70.445 -12.232,-78.765 ; -14.847,-70.445 -11.978,-78.765 ; -14.593,-70.445 -11.724,-78.765 ; -14.456,-70.69 -1.463,-70.69 ; -14.339,-70.445 -11.47,-78.765 ; -14.085,-70.445 -11.216,-78.765 ; -13.958,-70.445 -11.089,-78.765 ; -13.756,-70.436 -10.867,-78.815 ; -7.432,-76.656 -2.127,-70.535 ; -7.432,-76.275 -2.127,-70.154 ; -7.305,-77.037 -2,-70.916 ; -7.305,-76.783 -2,-70.662 ; -7.305,-75.894 -2,-69.773 ; -7.251,-77.228 -2,-71.17 ; -7.233,-75.466 -1.928,-69.345 ; -7.178,-77.418 -1.873,-71.297 ; -7.051,-77.545 -1.746,-71.424 ; -6.924,-77.672 -1.619,-71.551 ; -6.797,-77.799 -1.492,-71.678 ; -6.67,-78.18 -1.365,-72.059 ; -6.67,-77.926 -1.365,-71.805 ; -6.534,-78.316 -1.111,-72.059 ; -5.523,-78.927 cw(c-4.79,-76.378) -6.594,-74.435 -4.229,-71.706 ccw(c-4.559,-71.244) -4.585,-70.677 ; -3.902,-75.548 ccw(c-3.604,-76.005) -3.499,-76.54 ; -1.995,-66.525 cw(c-1.758,-69.127) 0.668,-68.157
  lines w0.3: -13.203,-78.815 -10.867,-78.815 ; 6.558,-82.906 6.558,-62.906 ; 6.558,-77.906 66.558,-77.906 ; 6.558,-72.906 66.558,-72.906 ; 6.558,-67.906 66.558,-67.906 ; 26.558,-82.906 26.558,-67.906 ; -23.442,-82.906 -23.442,-62.906 66.558,-62.906 66.558,-82.906 -23.442,-82.906
  text "Project: '.Board_Name'" at 65.364,-66.122 h3
  text "Gerber:" at 25.375,-71.206 h3
  text "Layer:" at 65.364,-71.206 h3
  text "Ref: '.Board_Reference'" at 25.375,-76.206 h3
  text "Variant: '.VariantName'" at 65.364,-76.206 h3
  text "R" at -19.751,-78.688 h1.52
  text "Rev: '.Board_PCB_Revision'" at 25.432,-81.206 h3
  text "Date: '.Board_Document_Date'" at 65.364,-81.206 h3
